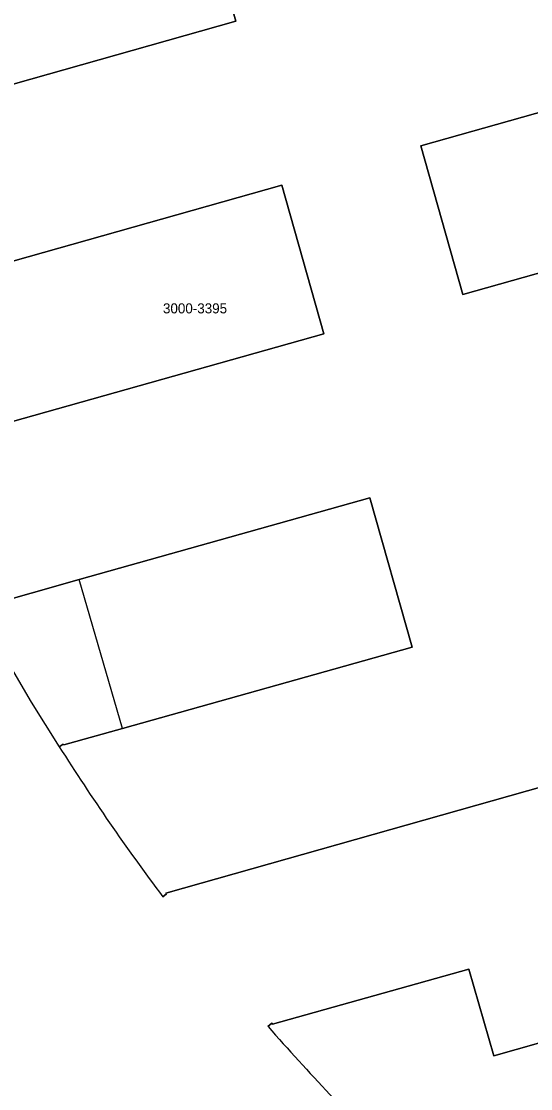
# Model space of a CAD drawing. Extents: x 155018 to 156648, y 383979 to 385733.
# Drawn here: x 156122.6 to 156173.4, y 384521.3 to 384627.6 of the extents above; entities that cross this region are included whole.
import ezdxf

# ---------------------------------------------------------------- set-up
doc = ezdxf.new("R2010")
doc.units = 0
for name, color, linetype in [('IMGEO_Erf', 7, 'Continuous'), ('IMGEO_Pand', 7, 'Continuous'), ('IMGEO_Pand_nummerreeks', 7, 'Continuous'), ('IMGEO_Pand_overbouw', 7, 'Continuous')]:
    doc.layers.add(name, color=color, linetype=linetype)

msp = doc.modelspace()

# ---------------------------------------------------------------- linework, layer by layer
at = {"layer": 'IMGEO_Erf'}
for points in [[(156099.76, 384615.33), (156100.27, 384615.41), (156100.29, 384615.32), (156108.15, 384617.54), (156143.99, 384627.66), (156139.81, 384642.54), (156103.95, 384632.44), (156098.36, 384630.84), (156098.35, 384630.74), (156097.9, 384630.78)], [(156206.07, 384627.43), (156205.61, 384627.3), (156205.58, 384627.4), (156162.46, 384615.25), (156166.65, 384600.43), (156208.13, 384612.11), (156208.11, 384612.21), (156208.62, 384612.3)], [(156110.77, 384584.7), (156111.18, 384584.9), (156111.22, 384584.81), (156152.77, 384596.51), (156148.6, 384611.32), (156105.39, 384599.14), (156105.43, 384599.05), (156105.01, 384598.92)], [(156126.4, 384555.38), (156126.8, 384555.63), (156126.85, 384555.55), (156132.69, 384557.19), (156161.57, 384565.31), (156157.37, 384580.18), (156128.38, 384572.02), (156118.79, 384569.32), (156118.83, 384569.23), (156118.42, 384568.99)], [(156209.58, 384561), (156209.13, 384561.07), (156209.14, 384561.17), (156137.04, 384540.79), (156137.1, 384540.71), (156136.72, 384540.43)], [(156147.21, 384527.5), (156147.59, 384527.82), (156147.66, 384527.74), (156167.24, 384533.2), (156169.71, 384524.59), (156189.75, 384530.27), (156187.32, 384538.91), (156206.97, 384544.58), (156207.39, 384544.51)]]:
    msp.add_lwpolyline(points, dxfattribs=at)
for centre, radius, start, end in [((156322.62, 384679.83), 232.36, 212.3847, 216.8644), ((156326.37, 384684.62), 238.29, 221.2516, 225.6535)]:
    msp.add_arc(centre, radius, start, end, dxfattribs=at)
at = {"layer": 'IMGEO_Pand'}
for points in [[(156097.9, 384630.78), (156098.35, 384630.74), (156098.36, 384630.84), (156103.95, 384632.44), (156139.81, 384642.54), (156143.99, 384627.66), (156108.15, 384617.54), (156100.29, 384615.32), (156100.27, 384615.41), (156099.76, 384615.33)], [(156208.62, 384612.3), (156208.11, 384612.21), (156208.13, 384612.11), (156166.65, 384600.43), (156162.46, 384615.25), (156205.58, 384627.4), (156205.61, 384627.3), (156206.07, 384627.43)], [(156105.01, 384598.92), (156105.43, 384599.05), (156105.39, 384599.14), (156148.6, 384611.32), (156152.77, 384596.51), (156111.22, 384584.81), (156111.18, 384584.9), (156110.77, 384584.7)], [(156118.42, 384568.99), (156118.83, 384569.23), (156118.79, 384569.32), (156128.38, 384572.02), (156157.37, 384580.18), (156161.57, 384565.31), (156132.69, 384557.19), (156126.85, 384555.55), (156126.8, 384555.63), (156126.4, 384555.38)], [(156136.72, 384540.43), (156137.1, 384540.71), (156137.04, 384540.79), (156209.14, 384561.17), (156209.13, 384561.07), (156209.58, 384561)], [(156207.39, 384544.51), (156206.97, 384544.58), (156187.32, 384538.91), (156189.75, 384530.27), (156169.71, 384524.59), (156167.24, 384533.2), (156147.66, 384527.74), (156147.59, 384527.82), (156147.21, 384527.5)]]:
    msp.add_lwpolyline(points, dxfattribs=at)
for centre, radius, start, end in [((156322.62, 384679.83), 232.36, 212.3847, 216.8644), ((156326.37, 384684.62), 238.29, 221.2516, 225.6535)]:
    msp.add_arc(centre, radius, start, end, dxfattribs=at)
at = {"layer": 'IMGEO_Pand_overbouw'}
msp.add_lwpolyline([(156118.42, 384568.99), (156120.94, 384564.37), (156123.6, 384559.83), (156126.4, 384555.38), (156126.8, 384555.63), (156126.85, 384555.55), (156132.69, 384557.19), (156128.38, 384572.02), (156118.79, 384569.32), (156118.83, 384569.23)], close=True, dxfattribs=at)

# ---------------------------------------------------------------- texts
at = {"layer": 'IMGEO_Pand_nummerreeks'}
msp.add_text('3000-3395', height=1, dxfattribs=at).set_placement((156136.74, 384598.55))

doc.saveas('drawing.dxf')
